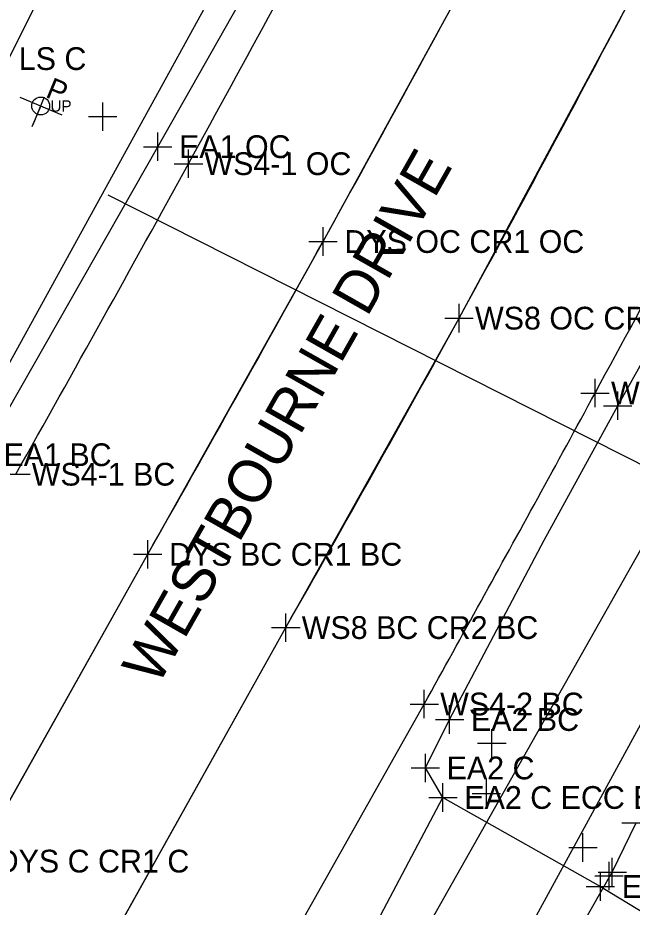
# Model space of a CAD drawing. Extents: x 1363693 to 1365209, y 422201 to 424153.
# Drawn here: x 1364140.7 to 1364183.9, y 422835.7 to 422898.3 of the extents above; entities that cross this region are included whole.
import ezdxf

# ---------------------------------------------------------------- set-up
doc = ezdxf.new("R2010")
doc.units = 0
for name, color, linetype in [('DR_X_Ditch', 7, 'Continuous'), ('DR_X_Storm_Sewer', 7, 'Continuous'), ('O-ALGN-BASELINE-WERK-CL-RW', 7, 'Continuous'), ('OWNERS', 7, 'Continuous'), ('PM_X_Channelizing_Line', 7, 'Continuous'), ('PM_X_CL_Double_Solid', 7, 'Continuous'), ('PM_X_Edge_Line', 7, 'Continuous'), ('RD_X_Text', 7, 'Continuous'), ('SN_X_Public', 7, 'Continuous'), ('SV_X_Original_Ground', 7, 'Continuous'), ('SV_X_Random_Point', 7, 'Continuous'), ('SV_X_Shot_Marker', 7, 'Continuous'), ('UT_X_FO', 7, 'Continuous'), ('UT_X_Gas', 7, 'Continuous'), ('UT_X_Misc_Cells', 7, 'Continuous'), ('UT_X_Sanitary_Line', 7, 'Continuous'), ('UT_X_Unknown_Cells', 7, 'Continuous'), ('UT_X_Water', 7, 'Continuous')]:
    doc.layers.add(name, color=color, linetype=linetype)

msp = doc.modelspace()

# ---------------------------------------------------------------- linework, layer by layer
at = {"layer": 'DR_X_Ditch'}
msp.add_line((1364182.525, 422838.212), (1364184.213, 422841.671), dxfattribs=at)
msp.add_line((1364182.525, 422838.212), (1364184.213, 422841.671), dxfattribs=at)
at = {"layer": 'DR_X_Storm_Sewer'}
msp.add_line((1364172.293, 422820.261), (1364182.525, 422838.212), dxfattribs=at)
msp.add_line((1364172.293, 422820.261), (1364182.525, 422838.212), dxfattribs=at)
at = {"layer": 'O-ALGN-BASELINE-WERK-CL-RW'}
for points in [[(1364112.961, 422795.674), (1364125.29, 422817.23), (1364137.711, 422838.984), (1364149.842, 422860.568), (1364162.178, 422882.564), (1364162.178, 422882.564), (1364174.207, 422904.529), (1364174.207, 422904.529), (1364181.519, 422918.743), (1364181.519, 422918.743), (1364185.177, 422926.315), (1364185.177, 422926.315), (1364194.648, 422946.825), (1364194.648, 422946.825), (1364195.429, 422948.569), (1364195.429, 422948.569), (1364199.632, 422958.68), (1364199.632, 422958.68), (1364204.422, 422971.255), (1364204.422, 422971.255), (1364205.193, 422973.458), (1364205.193, 422973.458), (1364212.224, 422994.557)], [(1364122.785, 422790.021), (1364135.008, 422811.616), (1364147.261, 422833.424), (1364159.557, 422855.412), (1364171.751, 422877.174), (1364171.751, 422877.174), (1364183.69, 422899.377), (1364183.69, 422899.377), (1364191.074, 422913.682), (1364191.074, 422913.682), (1364194.915, 422921.393), (1364194.915, 422921.393), (1364205.021, 422942.208), (1364205.021, 422942.208), (1364205.83, 422943.916), (1364205.83, 422943.916), (1364209.883, 422953.388), (1364209.883, 422953.388), (1364215.07, 422967.388), (1364215.07, 422967.388), (1364215.916, 422969.927), (1364215.916, 422969.927), (1364222.66, 422991.181)]]:
    msp.add_lwpolyline(points, dxfattribs=at)
at = {"layer": 'OWNERS'}
for points in [[(1364089.632, 422780.271), (1364102.08, 422801.911), (1364114.271, 422823.678), (1364126.868, 422845.272), (1364138.192, 422867.568), (1364150.546, 422889.234), (1364150.546, 422889.234), (1364162.879, 422910.978), (1364162.879, 422910.978), (1364170.332, 422924.545), (1364170.332, 422924.545), (1364173.925, 422931.803), (1364173.925, 422931.803), (1364182.923, 422951.414), (1364182.923, 422951.414), (1364183.888, 422953.606), (1364183.888, 422953.606), (1364188.472, 422964.837), (1364188.472, 422964.837), (1364192.543, 422975.639), (1364192.543, 422975.639), (1364193.28, 422977.776), (1364193.28, 422977.776), (1364200.007, 422998.363)], [(1364139.16, 422793.068), (1364146.3, 422805.509), (1364158.984, 422827.195), (1364162.097, 422827.35), (1364170.617, 422843.461), (1364169.375, 422845.537), (1364171.082, 422848.945), (1364177.735, 422861.55), (1364177.735, 422861.55), (1364182.909, 422871.012), (1364182.909, 422871.012), (1364186.616, 422877.647), (1364186.616, 422877.647), (1364186.928, 422878.215), (1364186.928, 422878.215), (1364190.13, 422884.197), (1364190.13, 422884.197), (1364194.847, 422893.032), (1364194.847, 422893.032), (1364196.148, 422895.451), (1364196.148, 422895.451), (1364197.195, 422897.398), (1364197.195, 422897.398), (1364198.38, 422899.656)], [(1364170.617, 422843.461), (1364181.694, 422837.203), (1364186.943, 422834.018)]]:
    msp.add_lwpolyline(points, dxfattribs=at)
at = {"layer": 'PM_X_Channelizing_Line'}
for p, q in [((1364137.711, 422838.984), (1364149.842, 422860.568)), ((1364147.261, 422833.424), (1364159.557, 422855.412)), ((1364147.261, 422833.424), (1364159.557, 422855.412)), ((1364156.986, 422828.186), (1364169.298, 422850.036))]:
    msp.add_line(p, q, dxfattribs=at)
for centre, radius, start, end in [((1362105.186, 424012.71), 2336.073, 331.220732, 331.834341), ((1361982.965, 424090.273), 2491.492, 331.004994, 331.580903), ((1362906.682, 423571.739), 1443.198, 331.231766, 332.232606), ((1362906.682, 423571.739), 1443.198, 331.231766, 332.232606), ((1210460.441, 506202.417), 174854.461, 331.53833418, 331.54620004), ((1362105.186, 424012.71), 2336.073, 330.607716, 331.220732), ((1361982.965, 424090.273), 2491.492, 330.42504, 331.004994), ((1362906.682, 423571.739), 1443.198, 330.241403, 331.231766), ((1362906.682, 423571.739), 1443.198, 330.241403, 331.231766), ((1362916.63, 423557.484), 1438.561, 331.202482, 331.538334), ((1359335.106, 425526.241), 5525.531, 331.031116, 331.202482)]:
    msp.add_arc(centre, radius, start, end, dxfattribs=at)
at = {"layer": 'PM_X_CL_Double_Solid'}
msp.add_line((1364137.711, 422838.984), (1364149.842, 422860.568), dxfattribs=at)
for start, end in [(331.004994, 331.580903), (330.42504, 331.004994)]:
    msp.add_arc((1361982.965, 424090.273), 2491.492, start, end, dxfattribs=at)
at = {"layer": 'PM_X_Edge_Line'}
msp.add_line((1364156.986, 422828.186), (1364169.298, 422850.036), dxfattribs=at)
for centre, radius, start, end in [((1362105.186, 424012.71), 2336.073, 331.220732, 331.834341), ((1210460.441, 506202.417), 174854.461, 331.53833418, 331.54620004), ((1362105.186, 424012.71), 2336.073, 330.607716, 331.220732), ((1362916.63, 423557.484), 1438.561, 331.202482, 331.538334), ((1359335.106, 425526.241), 5525.531, 331.031116, 331.202482)]:
    msp.add_arc(centre, radius, start, end, dxfattribs=at)
at = {"layer": 'SN_X_Public'}
for p, q in [((1364140.833, 422892.712), (1364143.787, 422891.482)), ((1364142.31, 422892.097), (1364141.695, 422890.62))]:
    msp.add_line(p, q, dxfattribs=at)
at = {"layer": 'SV_X_Original_Ground'}
for p, q in [((1364146.674, 422890.352), (1364146.674, 422892.352)), ((1364145.674, 422891.352), (1364147.674, 422891.352)), ((1364152.71, 422887.039), (1364152.71, 422889.039)), ((1364151.71, 422888.039), (1364153.71, 422888.039)), ((1364162.178, 422881.564), (1364162.178, 422883.564)), ((1364161.178, 422882.564), (1364163.178, 422882.564)), ((1364171.751, 422876.174), (1364171.751, 422878.174)), ((1364170.751, 422877.174), (1364172.751, 422877.174)), ((1364181.321, 422870.908), (1364181.321, 422872.908)), ((1364180.321, 422871.908), (1364182.321, 422871.908)), ((1364139.56, 422866.197), (1364141.56, 422866.197)), ((1364149.842, 422859.568), (1364149.842, 422861.568)), ((1364148.842, 422860.568), (1364150.842, 422860.568)), ((1364159.557, 422854.412), (1364159.557, 422856.412)), ((1364158.557, 422855.412), (1364160.557, 422855.412)), ((1364169.298, 422849.036), (1364169.298, 422851.036)), ((1364168.298, 422850.036), (1364170.298, 422850.036)), ((1364174.055, 422846.277), (1364174.055, 422848.277)), ((1364173.055, 422847.277), (1364175.055, 422847.277)), ((1364173.667, 422842.739), (1364173.667, 422844.739)), ((1364172.667, 422843.739), (1364174.667, 422843.739)), ((1364180.461, 422838.944), (1364180.461, 422840.944)), ((1364179.461, 422839.944), (1364181.461, 422839.944)), ((1364182.3, 422836.94), (1364182.3, 422838.94)), ((1364181.3, 422837.94), (1364183.3, 422837.94))]:
    msp.add_line(p, q, dxfattribs=at)
at = {"layer": 'SV_X_Shot_Marker'}
for p, q in [((1364150.546, 422888.234), (1364150.546, 422890.234)), ((1364149.546, 422889.234), (1364151.546, 422889.234)), ((1364182.909, 422870.012), (1364182.909, 422872.012)), ((1364181.909, 422871.012), (1364183.909, 422871.012)), ((1364171.082, 422847.945), (1364171.082, 422849.945)), ((1364170.082, 422848.945), (1364172.082, 422848.945)), ((1364169.375, 422844.537), (1364169.375, 422846.537)), ((1364168.375, 422845.537), (1364170.375, 422845.537)), ((1364170.617, 422842.461), (1364170.617, 422844.461)), ((1364169.617, 422843.461), (1364171.617, 422843.461)), ((1364183.213, 422841.671), (1364185.213, 422841.671)), ((1364182.525, 422837.212), (1364182.525, 422839.212)), ((1364181.525, 422838.212), (1364183.525, 422838.212)), ((1364181.694, 422836.203), (1364181.694, 422838.203)), ((1364180.694, 422837.203), (1364182.694, 422837.203))]:
    msp.add_line(p, q, dxfattribs=at)
at = {"layer": 'UT_X_FO'}
msp.add_lwpolyline([(1364198.41, 423083.145), (1364202.916, 423079.215), (1364206.614, 423072.625), (1364206.927, 423065.384), (1364205.607, 423052.889), (1364202.652, 423033.176), (1364193.585, 423006.537), (1364182.955, 422981.103), (1364130.325, 422876.058), (1364040.63, 422724.214)], dxfattribs=at)
at = {"layer": 'UT_X_Gas'}
msp.add_line((1364205.869, 422856.111), (1364147.056, 422885.823), dxfattribs=at)
msp.add_lwpolyline([(1364207.557, 423089.372), (1364211.518, 423072.856), (1364208.943, 423046.381), (1364201.649, 423012.485), (1364191.712, 422981.617), (1364181.14, 422953.292), (1364166.466, 422921.961), (1364127.708, 422851.525), (1364051.86, 422717.903)], dxfattribs=at)
at = {"layer": 'UT_X_Sanitary_Line'}
msp.add_lwpolyline([(1364014.261, 422733.758), (1364095.069, 422702.67), (1364258.083, 422991.019), (1364292.624, 423022.755)], dxfattribs=at)
at = {"layer": 'UT_X_Unknown_Cells'}
msp.add_line((1364141.776, 422890.803), (1364142.579, 422892.748), dxfattribs=at)
msp.add_circle((1364142.31, 422892.097), 0.63, dxfattribs=at)
at = {"layer": 'UT_X_Water'}
msp.add_lwpolyline([(1364263.889, 423134.469), (1364270.338, 423133.178), (1364266, 423070.885), (1364241.238, 422967.415), (1364211.801, 422898.599), (1364139.416, 422765.962), (1364094.46, 422690.2)], dxfattribs=at)

# ---------------------------------------------------------------- texts
at = {"layer": 'RD_X_Text'}
msp.add_text('WESTBOURNE DRIVE', height=3, rotation=60.41666, dxfattribs=at).set_placement((1364150.532, 422851.219))
at = {"layer": 'SV_X_Original_Ground'}
for s, p in [('WS4-1 OC', (1364153.829, 422887.239)), ('DYS OC CR1 OC', (1364163.678, 422881.764)), ('WS8 OC CR2 OC', (1364172.87, 422876.374)), ('WS4-2 OC', (1364182.44, 422871.108)), ('WS4-1 BC', (1364141.679, 422865.397)), ('DYS BC CR1 BC', (1364151.342, 422859.768)), ('WS8 BC CR2 BC', (1364160.676, 422854.612)), ('WS4-2 BC', (1364170.417, 422849.236)), ('DYS C CR1 C', (1364139.211, 422838.184))]:
    msp.add_text(s, height=1.6, dxfattribs=at).set_placement(p)
at = {"layer": 'SV_X_Random_Point'}
msp.add_text('LS C', height=1.6, dxfattribs=at).set_placement((1364140.767, 422894.628))
at = {"layer": 'SV_X_Shot_Marker'}
for s, p in [('EA1 OC', (1364152.046, 422888.434)), ('EA1 BC', (1364139.692, 422866.768)), ('EA2 BC', (1364172.582, 422848.145)), ('EA2 C', (1364170.875, 422844.737)), ('EA2 C ECC B', (1364172.117, 422842.661)), ('ECC C', (1364183.194, 422836.403))]:
    msp.add_text(s, height=1.6, dxfattribs=at).set_placement(p)
at = {"layer": 'UT_X_Misc_Cells'}
msp.add_text('UP', height=0.8, dxfattribs=at).set_placement((1364142.999, 422891.697))
at = {"layer": 'UT_X_Unknown_Cells'}
msp.add_text('P', height=1.503, rotation=337.58271, dxfattribs=at).set_placement((1364142.579, 422892.748))

doc.saveas('drawing.dxf')
